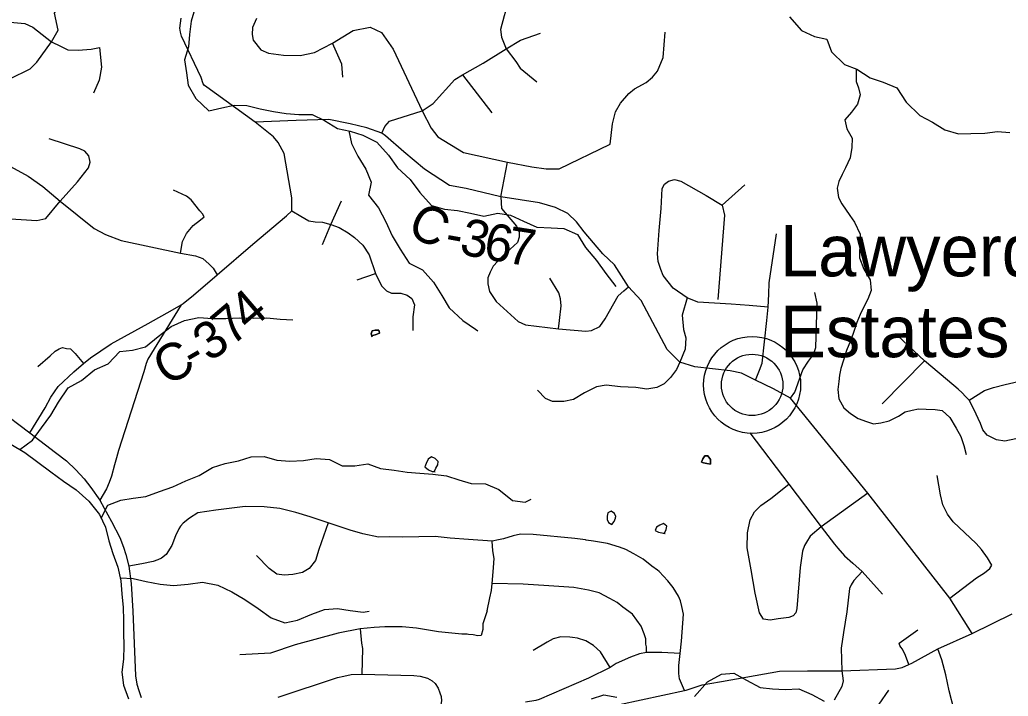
# Model space of a CAD drawing. Extents: x 0 to 34, y 0 to 22.
# Drawn here: x 4.119 to 4.877, y 16.654 to 17.173 of the extents above; entities that cross this region are included whole.
import ezdxf

# ---------------------------------------------------------------- set-up
doc = ezdxf.new("R2010")
doc.units = 0
for name, color, linetype in [('GM_X_County_Road', 7, 'Continuous'), ('GM_X_County_Road_Text', 7, 'Continuous'), ('GM_X_Minor_Lake', 7, 'Continuous'), ('GM_X_Minor_River', 7, 'Continuous'), ('GM_X_Township_Road', 7, 'Continuous'), ('GM_X_Unincorporated', 7, 'Continuous'), ('GM_X_Unincorporated_Location', 7, 'Continuous'), ('GM_X_Unincorporated_Text', 7, 'Continuous')]:
    doc.layers.add(name, color=color, linetype=linetype)

msp = doc.modelspace()

# ---------------------------------------------------------------- linework, layer by layer
at = {"layer": 'GM_X_County_Road'}
for points in [[(4.12664, 16.85638), (4.13839, 16.87556), (4.14269, 16.88366), (4.14851, 16.89173), (4.16036, 16.90312), (4.16795, 16.90955), (4.17313, 16.91393), (4.18903, 16.92469), (4.21733, 16.9402), (4.23607, 16.95072), (4.24264, 16.95456), (4.2443, 16.95553), (4.25217, 16.96205), (4.27045, 16.97768), (4.29779, 17.00108), (4.32347, 17.02281), (4.32772, 17.02682), (4.32767, 17.03679), (4.32171, 17.07077), (4.31723, 17.07925), (4.31365, 17.08352), (4.29944, 17.0948), (4.26253, 17.12154), (4.26075, 17.12282), (4.25973, 17.12424), (4.2581, 17.12902), (4.24307, 17.16077), (4.2423, 17.16397), (4.24185, 17.16705), (4.24273, 17.17463)], [(4.84964, 16.70226), (4.83244, 16.72926), (4.76946, 16.80997), (4.71038, 16.88296), (4.69718, 16.89015), (4.68339, 16.89672), (4.6727, 16.90215), (4.66406, 16.90383), (4.63694, 16.90695), (4.62542, 16.91055), (4.61559, 16.92015), (4.59567, 16.95783), (4.58609, 16.96825), (4.57527, 16.98518), (4.56639, 16.99358), (4.55199, 17.01062), (4.54599, 17.0183), (4.53951, 17.02454), (4.52992, 17.02934), (4.51768, 17.03294), (4.4881, 17.03739), (4.46152, 17.04374), (4.44856, 17.04614), (4.42937, 17.05862), (4.41367, 17.07192), (4.39948, 17.08416), (4.39662, 17.08634), (4.38518, 17.09046), (4.37236, 17.09343), (4.356, 17.09675), (4.33105, 17.09606), (4.29944, 17.0948)], [(4.10198, 16.87463), (4.12664, 16.85638)], [(4.12664, 16.85638), (4.14645, 16.84118), (4.15484, 16.83476), (4.16207, 16.82778), (4.16832, 16.82087), (4.17358, 16.81421), (4.18024, 16.80459), (4.18377, 16.79851), (4.1892, 16.78824), (4.19561, 16.77583), (4.19857, 16.76843), (4.20021, 16.76284), (4.20252, 16.75396), (4.20433, 16.74064), (4.20572, 16.71927), (4.20778, 16.6697), (4.20885, 16.66337), (4.21016, 16.65852), (4.21197, 16.65301)], [(4.56252, 16.64419), (4.62886, 16.65843), (4.63009, 16.65869), (4.6364, 16.66083), (4.64252, 16.66278), (4.64843, 16.66398), (4.65738, 16.66548), (4.70177, 16.67321), (4.72322, 16.6737), (4.74956, 16.67366), (4.79081, 16.67517), (4.79596, 16.67619), (4.80092, 16.6784), (4.80324, 16.67944), (4.8232, 16.69058), (4.84964, 16.70226), (4.88038, 16.71739)]]:
    msp.add_lwpolyline(points, dxfattribs=at)
at = {"layer": 'GM_X_Minor_Lake'}
for points in [[(4.38979, 16.93102), (4.39226, 16.93178), (4.39493, 16.93273), (4.39436, 16.9352), (4.39169, 16.9352), (4.38922, 16.93463), (4.38846, 16.93216), (4.38922, 16.93064)], [(4.38922, 16.92969), (4.38846, 16.93216), (4.38922, 16.93463), (4.39169, 16.9352), (4.39436, 16.9352), (4.39493, 16.93273), (4.39226, 16.93178), (4.38979, 16.93102), (4.38922, 16.93064)], [(4.38922, 16.93064), (4.38979, 16.93102)], [(4.43486, 16.83779), (4.43239, 16.83608), (4.43068, 16.83285), (4.42973, 16.83018), (4.43258, 16.8279), (4.43524, 16.82657), (4.43714, 16.82676)], [(4.43714, 16.82676), (4.4381, 16.82923), (4.43962, 16.8317), (4.44, 16.83418), (4.43753, 16.83646), (4.43486, 16.83779), (4.43239, 16.83608), (4.43068, 16.83285), (4.42973, 16.83018), (4.43258, 16.8279), (4.43524, 16.82657), (4.43753, 16.82638)], [(4.43714, 16.82676), (4.4381, 16.82923), (4.43962, 16.8317), (4.44, 16.83418), (4.43753, 16.83646), (4.43486, 16.83779)], [(4.64694, 16.83856), (4.64446, 16.83875), (4.64294, 16.83627), (4.64194, 16.83368)], [(4.64194, 16.83368), (4.64351, 16.83323), (4.64599, 16.83266), (4.64884, 16.83228), (4.64884, 16.8357), (4.64694, 16.83856)], [(4.64199, 16.8338), (4.64294, 16.83627), (4.64446, 16.83875), (4.64694, 16.83856), (4.64884, 16.8357), (4.64884, 16.83228), (4.64599, 16.83266), (4.64351, 16.83323), (4.64218, 16.83361)], [(4.57629, 16.79213), (4.57523, 16.79442), (4.57257, 16.79613), (4.57009, 16.79499), (4.56952, 16.79232), (4.56971, 16.78985), (4.57066, 16.78738), (4.57314, 16.78586)], [(4.57637, 16.79194), (4.57523, 16.79442), (4.57257, 16.79613), (4.57009, 16.79499), (4.56952, 16.79232), (4.56971, 16.78985), (4.57066, 16.78738), (4.57314, 16.78586), (4.57504, 16.78833), (4.57599, 16.7908), (4.57637, 16.79251)], [(4.57314, 16.78586), (4.57504, 16.78833), (4.57599, 16.7908), (4.57629, 16.79213)], [(4.61289, 16.78662), (4.61004, 16.78548), (4.60756, 16.78376), (4.60642, 16.78129), (4.60889, 16.78015), (4.61156, 16.77958), (4.61343, 16.77914)], [(4.61346, 16.7792), (4.61479, 16.78205), (4.61536, 16.78452), (4.61289, 16.78662), (4.61004, 16.78548), (4.60756, 16.78376), (4.60642, 16.78129), (4.60889, 16.78015), (4.61156, 16.77958), (4.61403, 16.77901), (4.61422, 16.77901)], [(4.61343, 16.77914), (4.61479, 16.78205), (4.61536, 16.78452), (4.61289, 16.78662)]]:
    msp.add_lwpolyline(points, dxfattribs=at)
at = {"layer": 'GM_X_Minor_River'}
for points in [[(4.25324, 17.18177), (4.25039, 17.17226), (4.24906, 17.16218), (4.24849, 17.15248), (4.24525, 17.14258), (4.24677, 17.13269), (4.2481, 17.12318), (4.254, 17.1129), (4.26408, 17.10358), (4.27397, 17.10586), (4.28348, 17.10777), (4.29318, 17.10757), (4.30326, 17.1051), (4.31372, 17.10301), (4.32323, 17.10149), (4.33293, 17.10054), (4.3432, 17.10054), (4.35271, 17.09597), (4.3626, 17.08988), (4.3723, 17.08798), (4.38219, 17.08474), (4.39284, 17.07942), (4.40178, 17.06933), (4.40882, 17.05982), (4.41833, 17.05088), (4.42575, 17.0408), (4.43488, 17.0309), (4.44477, 17.02786), (4.45466, 17.02691), (4.46474, 17.02481), (4.47501, 17.02253), (4.48566, 17.025), (4.49555, 17.02329), (4.50544, 17.01873), (4.51552, 17.01416), (4.52674, 17.01359), (4.53644, 17.01321), (4.5469, 17.00864), (4.55299, 16.99856), (4.56136, 16.98867), (4.56858, 16.97858), (4.5762, 16.96866)], [(4.70953, 17.17569), (4.71866, 17.16522), (4.72874, 17.16066), (4.73825, 17.15857), (4.74167, 17.14886), (4.75175, 17.13916), (4.76126, 17.13554), (4.77134, 17.12889), (4.78123, 17.12546), (4.79189, 17.12109), (4.79911, 17.11005), (4.80957, 17.09978), (4.81927, 17.09483), (4.82878, 17.08893), (4.83905, 17.0857), (4.84856, 17.08608), (4.8594, 17.08627), (4.86911, 17.0876), (4.87861, 17.08684)], [(4.76055, 17.13582), (4.76066, 17.13284), (4.76072, 17.12599), (4.76253, 17.12101), (4.76358, 17.11566), (4.76175, 17.10865), (4.75708, 17.10245), (4.75204, 17.09645), (4.75344, 17.08957), (4.75749, 17.08246), (4.75736, 17.07523), (4.75608, 17.06745), (4.75234, 17.05971), (4.74998, 17.05462), (4.74741, 17.04933), (4.74618, 17.04402), (4.74701, 17.03697), (4.74957, 17.03197), (4.75587, 17.02311), (4.75938, 17.0179), (4.76359, 17.00888), (4.76404, 17.00183), (4.76318, 16.99614), (4.76327, 16.99062), (4.76653, 16.9818), (4.77132, 16.97372), (4.77212, 16.96553), (4.76954, 16.95891), (4.76639, 16.9525), (4.76383, 16.94702), (4.76125, 16.94098), (4.75826, 16.93247), (4.75626, 16.92698), (4.75329, 16.91961), (4.75087, 16.91204), (4.74886, 16.90561), (4.74783, 16.90068), (4.74736, 16.89574), (4.74649, 16.88966), (4.74731, 16.88241), (4.75118, 16.87549), (4.75623, 16.87122), (4.76223, 16.8673), (4.76845, 16.86491), (4.77393, 16.86329), (4.77963, 16.86395), (4.78592, 16.86555), (4.793, 16.86904), (4.79819, 16.87237), (4.80372, 16.87379), (4.80848, 16.87466), (4.81436, 16.87455), (4.82118, 16.87424), (4.82667, 16.87338), (4.83246, 16.86795), (4.83744, 16.85986), (4.84093, 16.85352), (4.84328, 16.84644), (4.84505, 16.83955)], [(4.37138, 17.08816), (4.37344, 17.07847), (4.3782, 17.06876), (4.38447, 17.05868), (4.38866, 17.04879), (4.38656, 17.0387), (4.39417, 17.029), (4.39988, 17.01835), (4.40463, 17.0075), (4.41072, 16.99723), (4.41775, 16.98657), (4.42783, 16.98144), (4.43639, 16.97192), (4.44286, 16.96184), (4.44837, 16.95233), (4.45883, 16.94262), (4.46854, 16.93597), (4.47025, 16.93469)], [(4.11909, 16.84337), (4.12883, 16.85073), (4.13568, 16.86024), (4.14272, 16.86975), (4.14861, 16.87984), (4.15603, 16.89087), (4.1663, 16.89658), (4.1762, 16.90457), (4.18685, 16.90914), (4.19579, 16.91884), (4.2053, 16.91979), (4.21538, 16.92227), (4.22508, 16.93026), (4.23516, 16.93787), (4.24524, 16.94262), (4.25627, 16.94491), (4.26673, 16.94415), (4.277, 16.94415), (4.28727, 16.94453), (4.29831, 16.94434), (4.30858, 16.94453), (4.31866, 16.94357), (4.32846, 16.94301)], [(4.11209, 16.8475), (4.12274, 16.84122), (4.13283, 16.8338), (4.14272, 16.82638), (4.15242, 16.81915), (4.16231, 16.81249), (4.17201, 16.80393), (4.18018, 16.79365), (4.18475, 16.78376), (4.18722, 16.7733), (4.19045, 16.76378), (4.19407, 16.75313), (4.19635, 16.74266), (4.1973, 16.73258), (4.19825, 16.72231), (4.19844, 16.7126), (4.19844, 16.70271), (4.19882, 16.69282), (4.19844, 16.68254), (4.19729, 16.67246), (4.19863, 16.66257), (4.20224, 16.6521)], [(4.18146, 16.79089), (4.18646, 16.80088), (4.19635, 16.80469), (4.20586, 16.80621), (4.21575, 16.80754), (4.22621, 16.81116), (4.23629, 16.81496), (4.24637, 16.81953), (4.25665, 16.82352), (4.26692, 16.8298), (4.27662, 16.83285), (4.2867, 16.83475), (4.2964, 16.83779), (4.30648, 16.83817), (4.31618, 16.83532), (4.32607, 16.83456), (4.33653, 16.83513), (4.34623, 16.83646), (4.3565, 16.83589), (4.3662, 16.83094), (4.3759, 16.83094), (4.38598, 16.83247), (4.39568, 16.82885), (4.40614, 16.82771), (4.41622, 16.826), (4.42592, 16.82543), (4.43581, 16.82467), (4.44627, 16.82333), (4.45579, 16.8201), (4.46529, 16.81744), (4.47633, 16.81706), (4.4866, 16.81287), (4.49687, 16.80431), (4.50676, 16.80317), (4.51122, 16.80531)], [(4.19584, 16.74497), (4.20586, 16.74438), (4.21594, 16.74228), (4.22678, 16.74019), (4.23686, 16.73905), (4.24808, 16.74019), (4.25911, 16.74171), (4.27091, 16.73924), (4.28175, 16.73429), (4.29164, 16.7284), (4.30172, 16.72155), (4.3118, 16.71432), (4.32226, 16.71051), (4.33196, 16.71241), (4.34299, 16.71717), (4.35269, 16.7206), (4.36258, 16.72155), (4.37247, 16.71983), (4.38236, 16.71869), (4.38699, 16.7195)], [(4.63666, 16.65401), (4.64655, 16.66524), (4.65739, 16.67094), (4.6669, 16.6717), (4.6766, 16.66638), (4.68706, 16.66086), (4.69657, 16.65972), (4.70627, 16.65915), (4.71654, 16.65972), (4.72662, 16.65534), (4.73613, 16.65021)], [(4.55753, 16.65211), (4.56704, 16.65515), (4.57712, 16.65325)]]:
    msp.add_lwpolyline(points, dxfattribs=at)
at = {"layer": 'GM_X_Township_Road'}
for p, q in [((4.45859, 17.13121), (4.48121, 17.10194)), ((4.4881, 17.03739), (4.4932, 17.06414)), ((4.65782, 17.03102), (4.67534, 17.04662)), ((4.37768, 16.97369), (4.3918, 16.97855)), ((4.693, 16.95279), (4.67844, 16.95398)), ((4.78062, 16.87849), (4.81299, 16.91159)), ((4.77093, 16.63735), (4.78574, 16.65885))]:
    msp.add_line(p, q, dxfattribs=at)
for points in [[(4.1114, 17.12797), (4.12687, 17.1358), (4.13209, 17.14089), (4.14319, 17.1564), (4.14836, 17.16541), (4.14561, 17.17833), (4.15676, 17.19756)], [(4.52488, 17.1966), (4.50785, 17.19631), (4.50167, 17.19425), (4.49767, 17.19081), (4.49275, 17.18406), (4.49046, 17.17639), (4.48768, 17.16589), (4.48863, 17.15992), (4.49217, 17.15099), (4.49944, 17.14141), (4.50293, 17.13623), (4.51552, 17.12581)], [(3.84486, 17.01438), (3.87272, 17.04101), (3.88088, 17.05106), (3.89446, 17.06942), (3.91501, 17.08796), (3.93094, 17.10637), (3.94087, 17.11091), (4.0248, 17.14219), (4.05959, 17.15319), (4.07149, 17.15828), (4.07831, 17.16403), (4.0898, 17.17093), (4.09758, 17.17272), (4.12292, 17.17045), (4.12888, 17.16777), (4.14319, 17.1564), (4.15028, 17.15317), (4.15577, 17.15025), (4.16378, 17.14993), (4.17383, 17.15092), (4.18, 17.15202), (4.18171, 17.13709), (4.17985, 17.12695), (4.17547, 17.11693)], [(4.30045, 17.17437), (4.2975, 17.1674), (4.29726, 17.16205), (4.2981, 17.15773), (4.30387, 17.15017), (4.30978, 17.14769), (4.32134, 17.14615), (4.33398, 17.14592), (4.34507, 17.14816), (4.35881, 17.15533), (4.37465, 17.16517), (4.38785, 17.16757), (4.39649, 17.16349), (4.40537, 17.15077), (4.42766, 17.1034), (4.43465, 17.09006), (4.43976, 17.08348), (4.45936, 17.07158), (4.4932, 17.06414), (4.51168, 17.06054), (4.52272, 17.05886), (4.53268, 17.05899), (4.57191, 17.07781), (4.57361, 17.09342), (4.57596, 17.10261), (4.57987, 17.10926), (4.58632, 17.11688), (4.59052, 17.1204), (4.59961, 17.12529), (4.6044, 17.12939), (4.60822, 17.13399), (4.61247, 17.14453), (4.61415, 17.16397)], [(4.39662, 17.08634), (4.39914, 17.09137), (4.40269, 17.0956), (4.42766, 17.1034), (4.4361, 17.10911), (4.45269, 17.12753), (4.45859, 17.13121), (4.47444, 17.14), (4.49217, 17.15099), (4.50304, 17.15773), (4.5184, 17.16301)], [(4.36673, 17.12941), (4.36601, 17.13925), (4.35881, 17.15533)], [(4.10788, 17.02076), (4.13209, 17.01929), (4.139, 17.0207), (4.15004, 17.03414), (4.16313, 17.04885), (4.17176, 17.05975), (4.17283, 17.06414), (4.17187, 17.06894), (4.16895, 17.07239), (4.16507, 17.0742), (4.14152, 17.08196)], [(4.11188, 17.06078), (4.12532, 17.05334), (4.1366, 17.04542), (4.15004, 17.03414), (4.17597, 17.0132), (4.18483, 17.0085), (4.19669, 17.00402), (4.24237, 16.99422), (4.25382, 16.9921), (4.25947, 16.99024), (4.26417, 16.98572), (4.26724, 16.98265), (4.27045, 16.97768)], [(4.67844, 16.95398), (4.66485, 16.95508), (4.63922, 16.95668), (4.63095, 16.95999), (4.62015, 16.96743), (4.61256, 16.977), (4.61066, 16.98157), (4.60861, 16.98781), (4.60832, 16.99365), (4.60958, 17.01161), (4.61096, 17.02855), (4.61187, 17.04377), (4.61359, 17.04708), (4.61668, 17.04937), (4.62114, 17.05075), (4.62617, 17.0496), (4.64558, 17.03846), (4.65782, 17.03102), (4.65974, 17.02334), (4.65455, 16.95857)], [(4.24237, 16.99422), (4.24371, 17.00321), (4.24674, 17.00922), (4.25193, 17.01535), (4.25748, 17.01972), (4.26043, 17.02208), (4.25925, 17.02444), (4.25715, 17.02663), (4.25047, 17.03503), (4.24685, 17.03802), (4.23694, 17.04262)], [(4.35124, 17.00099), (4.35748, 17.01617), (4.3658, 17.03448)], [(4.4881, 17.03739), (4.48864, 17.02862), (4.50016, 17.01494), (4.50201, 17.01024), (4.50216, 17.00653), (4.50087, 17.00246), (4.4896, 16.99214), (4.4821, 16.98415), (4.47973, 16.97963), (4.47811, 16.97525), (4.47792, 16.97056), (4.47938, 16.96479), (4.48439, 16.95714), (4.50136, 16.94175), (4.50694, 16.93929), (4.53227, 16.93618), (4.55317, 16.93437), (4.55751, 16.93494), (4.56392, 16.93803), (4.56807, 16.94391), (4.57811, 16.96138), (4.58239, 16.96533), (4.58609, 16.96825)], [(4.32772, 17.02682), (4.33458, 17.02266), (4.34068, 17.01914), (4.34567, 17.01826), (4.35114, 17.01806), (4.35748, 17.01617), (4.36396, 17.01387), (4.37082, 17.00993), (4.37576, 17.00631), (4.38216, 17.0003), (4.38701, 16.99282), (4.3918, 16.97855), (4.39442, 16.97331), (4.39677, 16.96899), (4.40027, 16.96539), (4.40415, 16.96358), (4.41138, 16.96349), (4.41608, 16.96205), (4.41979, 16.95933), (4.42187, 16.95455), (4.42051, 16.94542), (4.42042, 16.93494)], [(4.68339, 16.89672), (4.6866, 16.9045), (4.68843, 16.90977), (4.69209, 16.9425), (4.693, 16.95279), (4.69369, 16.96286), (4.69391, 16.97136), (4.69941, 17.00909)], [(4.53227, 16.93618), (4.53304, 16.94247), (4.53425, 16.9538), (4.5337, 16.95927), (4.53245, 16.96382), (4.52559, 16.97511)], [(4.63095, 16.95999), (4.62711, 16.94655), (4.62807, 16.93551), (4.63007, 16.92922), (4.62938, 16.92052), (4.62542, 16.91055), (4.62274, 16.90496), (4.61816, 16.89878), (4.61336, 16.89398), (4.60763, 16.891), (4.60008, 16.88986), (4.59172, 16.89116), (4.57978, 16.89162), (4.56873, 16.89283), (4.56149, 16.89163), (4.55225, 16.88688), (4.54378, 16.88184), (4.5363, 16.88028), (4.52776, 16.88024), (4.52227, 16.88276), (4.51609, 16.88894)], [(4.71038, 16.88296), (4.71368, 16.88746), (4.71977, 16.90455), (4.72415, 16.91141), (4.72784, 16.91639), (4.72981, 16.92188), (4.73084, 16.95595), (4.72885, 16.96407)], [(4.24264, 16.95456), (4.21725, 16.91281), (4.21584, 16.90943), (4.21418, 16.90319), (4.19479, 16.84284), (4.19323, 16.83715), (4.19166, 16.83164), (4.1892, 16.82301), (4.18755, 16.81816), (4.18542, 16.81323), (4.18024, 16.80459)], [(4.9795, 16.74058), (4.96493, 16.80911), (4.96042, 16.83032), (4.95728, 16.83674), (4.95402, 16.84051), (4.9499, 16.8436), (4.93102, 16.85579), (4.92346, 16.85837), (4.91986, 16.85888), (4.91454, 16.85837), (4.87471, 16.84995), (4.86836, 16.85081), (4.86123, 16.85459), (4.85789, 16.85862), (4.856, 16.86352), (4.85081, 16.87456), (4.84724, 16.88137), (4.84458, 16.88429), (4.84192, 16.88695), (4.83891, 16.88969), (4.83565, 16.89253), (4.81299, 16.91159), (4.79239, 16.9309)], [(4.13289, 16.90709), (4.14218, 16.91543), (4.14615, 16.91903), (4.14918, 16.92073), (4.15184, 16.92168), (4.15487, 16.92111), (4.1579, 16.92073), (4.1615, 16.91713), (4.16795, 16.90955)], [(4.84724, 16.88137), (4.85909, 16.88867), (4.86604, 16.89107), (4.87488, 16.89339), (4.89497, 16.89794), (4.90218, 16.90094), (4.90725, 16.90619)], [(4.67917, 16.8563), (4.709, 16.81686), (4.73377, 16.78411), (4.74389, 16.77073), (4.74663, 16.76766)], [(4.83244, 16.72926), (4.85308, 16.74508), (4.85914, 16.74891), (4.86322, 16.75213), (4.86483, 16.75472), (4.86136, 16.76029), (4.85692, 16.76671), (4.85258, 16.77141), (4.83504, 16.78785), (4.83059, 16.79378), (4.82713, 16.80107), (4.82527, 16.80874), (4.8228, 16.82357)], [(4.76946, 16.80997), (4.73377, 16.78411), (4.72539, 16.77688), (4.72241, 16.77226), (4.72108, 16.76969), (4.71934, 16.76558), (4.71779, 16.75295), (4.71499, 16.72151), (4.71444, 16.71824), (4.7122, 16.71571), (4.7091, 16.71459), (4.70076, 16.71355), (4.69457, 16.71252), (4.68951, 16.71318), (4.68656, 16.71815), (4.6832, 16.73327), (4.67996, 16.75103), (4.67708, 16.76807), (4.67723, 16.77945), (4.6792, 16.78938), (4.68267, 16.79575), (4.68739, 16.80044), (4.69504, 16.80597), (4.709, 16.81686)], [(4.55345, 16.77397), (4.55298, 16.77404), (4.54488, 16.7752), (4.51288, 16.77834), (4.5031, 16.77846), (4.49748, 16.77723), (4.49011, 16.77502), (4.48611, 16.77405), (4.48136, 16.77302), (4.46317, 16.77428), (4.44926, 16.77554), (4.43759, 16.77679), (4.41253, 16.77611), (4.40246, 16.77634), (4.39422, 16.77622), (4.3822, 16.77874), (4.37248, 16.78149), (4.35565, 16.78721), (4.34181, 16.7919), (4.33071, 16.79522), (4.31846, 16.79819), (4.30656, 16.79957), (4.2918, 16.7998), (4.26937, 16.79705), (4.25564, 16.79476), (4.24921, 16.79087), (4.24428, 16.787), (4.24238, 16.7847), (4.24099, 16.78256), (4.23852, 16.77722), (4.23548, 16.76991), (4.23129, 16.76292), (4.22767, 16.76004), (4.22488, 16.75874), (4.22134, 16.75758), (4.21271, 16.75577), (4.20252, 16.75396)], [(4.35565, 16.78721), (4.34845, 16.76684), (4.34593, 16.75826), (4.34089, 16.75219), (4.33574, 16.749), (4.32853, 16.74762), (4.32178, 16.74693), (4.31626, 16.74782), (4.3104, 16.75215), (4.3005, 16.76215)], [(4.48165, 16.74346), (4.48239, 16.75288), (4.4829, 16.7598), (4.48193, 16.76564), (4.48136, 16.77302)], [(4.60817, 16.7508), (4.60375, 16.75404), (4.59734, 16.75929), (4.59007, 16.76346), (4.58389, 16.76673), (4.57897, 16.7685), (4.56984, 16.7714), (4.55906, 16.77316), (4.55345, 16.77397)], [(4.74663, 16.76766), (4.75177, 16.76189), (4.75801, 16.75625), (4.76519, 16.74983), (4.77184, 16.74247), (4.78072, 16.73239)], [(4.62886, 16.65843), (4.62512, 16.66735), (4.62456, 16.67147), (4.62447, 16.67775), (4.62549, 16.68686), (4.62662, 16.6964), (4.62812, 16.71712), (4.62681, 16.72302), (4.62578, 16.72724), (4.62424, 16.73079), (4.62034, 16.73755), (4.61603, 16.7428), (4.61294, 16.74636), (4.60937, 16.74992), (4.60817, 16.7508)], [(4.76519, 16.74983), (4.75875, 16.74299), (4.75689, 16.73958), (4.7554, 16.73672), (4.75337, 16.71898), (4.75081, 16.70309), (4.74925, 16.69098), (4.74956, 16.67366)], [(4.47753, 16.71975), (4.4797, 16.72965), (4.48096, 16.73537), (4.48142, 16.74052), (4.48165, 16.74346)], [(4.59981, 16.68764), (4.59965, 16.69202), (4.59929, 16.69405), (4.59916, 16.69818), (4.59794, 16.70212), (4.59569, 16.70784), (4.58904, 16.71712), (4.58163, 16.72249), (4.57722, 16.7261), (4.57173, 16.72918), (4.56348, 16.73355), (4.55536, 16.73563), (4.54402, 16.7376), (4.52478, 16.73889), (4.50518, 16.7402), (4.48142, 16.74052)], [(4.47753, 16.71975), (4.47432, 16.70955), (4.47415, 16.70533), (4.47283, 16.70075), (4.47037, 16.70035), (4.46683, 16.70127), (4.46327, 16.70158)], [(4.46327, 16.70158), (4.46225, 16.70167), (4.45813, 16.70167), (4.44011, 16.70345), (4.42323, 16.70636), (4.41224, 16.70745), (4.39908, 16.70745), (4.39074, 16.70698), (4.38015, 16.70588), (4.36332, 16.70241), (4.3303, 16.69346), (4.31119, 16.68725), (4.28782, 16.68588)], [(4.38015, 16.70588), (4.38123, 16.69475), (4.3818, 16.69069), (4.38128, 16.671)], [(4.57188, 16.67616), (4.5645, 16.68805), (4.55923, 16.69309), (4.55334, 16.69654), (4.54675, 16.69878), (4.54291, 16.69925), (4.54107, 16.69948), (4.53406, 16.69964), (4.52814, 16.69807), (4.52353, 16.69551), (4.51275, 16.68911)], [(4.80092, 16.6784), (4.79838, 16.68536), (4.79628, 16.69019), (4.795, 16.6917), (4.79409, 16.69311), (4.79351, 16.6948), (4.80783, 16.70512)], [(4.62549, 16.68686), (4.61153, 16.68776), (4.59981, 16.68764), (4.59449, 16.68653), (4.58759, 16.68398), (4.57657, 16.67916), (4.57188, 16.67616), (4.55538, 16.66795), (4.51741, 16.65158), (4.51492, 16.65087), (4.50692, 16.64954)], [(4.83578, 16.64332), (4.83187, 16.65822), (4.82934, 16.67051), (4.82645, 16.68208), (4.8232, 16.69058)], [(4.31706, 16.65329), (4.36267, 16.66844), (4.3675, 16.66958), (4.37311, 16.67086), (4.38128, 16.671), (4.42117, 16.66992), (4.42603, 16.66952), (4.43175, 16.66797), (4.43524, 16.66597), (4.43765, 16.66385), (4.43994, 16.6603), (4.44114, 16.65681), (4.44234, 16.65378), (4.44257, 16.65058), (4.44096, 16.64222)], [(4.74956, 16.67366), (4.75074, 16.66589), (4.74967, 16.66159), (4.74385, 16.65102)]]:
    msp.add_lwpolyline(points, dxfattribs=at)
at = {"layer": 'GM_X_Unincorporated'}
for radius in [0.0372, 0.02358]:
    msp.add_circle((4.68081, 16.89309), radius, dxfattribs=at)
at = {"layer": 'GM_X_Unincorporated_Location'}
msp.add_line((4.68081, 16.89309), (4.68081, 16.89309), dxfattribs=at)

# ---------------------------------------------------------------- texts
at = {"layer": 'GM_X_County_Road_Text'}
for s, rotation, p in [('C', 333.00033, (4.41481, 17.00946)), ('3', 347.76895, (4.45535, 16.99394)), ('6', 350.23936, (4.47377, 16.98998)), ('7', 351.14673, (4.4915, 16.98693)), ('-', 349.66957, (4.44412, 16.99599)), ('4', 40.63672, (4.29494, 16.9336)), ('7', 40.34353, (4.28148, 16.92217)), ('3', 34.12219, (4.26431, 16.91031)), ('C', 29.2995, (4.23163, 16.89171)), ('-', 29.90864, (4.25227, 16.90329))]:
    msp.add_text(s, height=0.02841, rotation=rotation, dxfattribs=at).set_placement(p)
at = {"layer": 'GM_X_Unincorporated_Text'}
for s, p in [('Lawyerdale', (4.70212, 16.97643)), ('Estates', (4.70212, 16.91435))]:
    msp.add_text(s, height=0.039489, rotation=0.00001, dxfattribs=at).set_placement(p)

doc.saveas('drawing.dxf')
